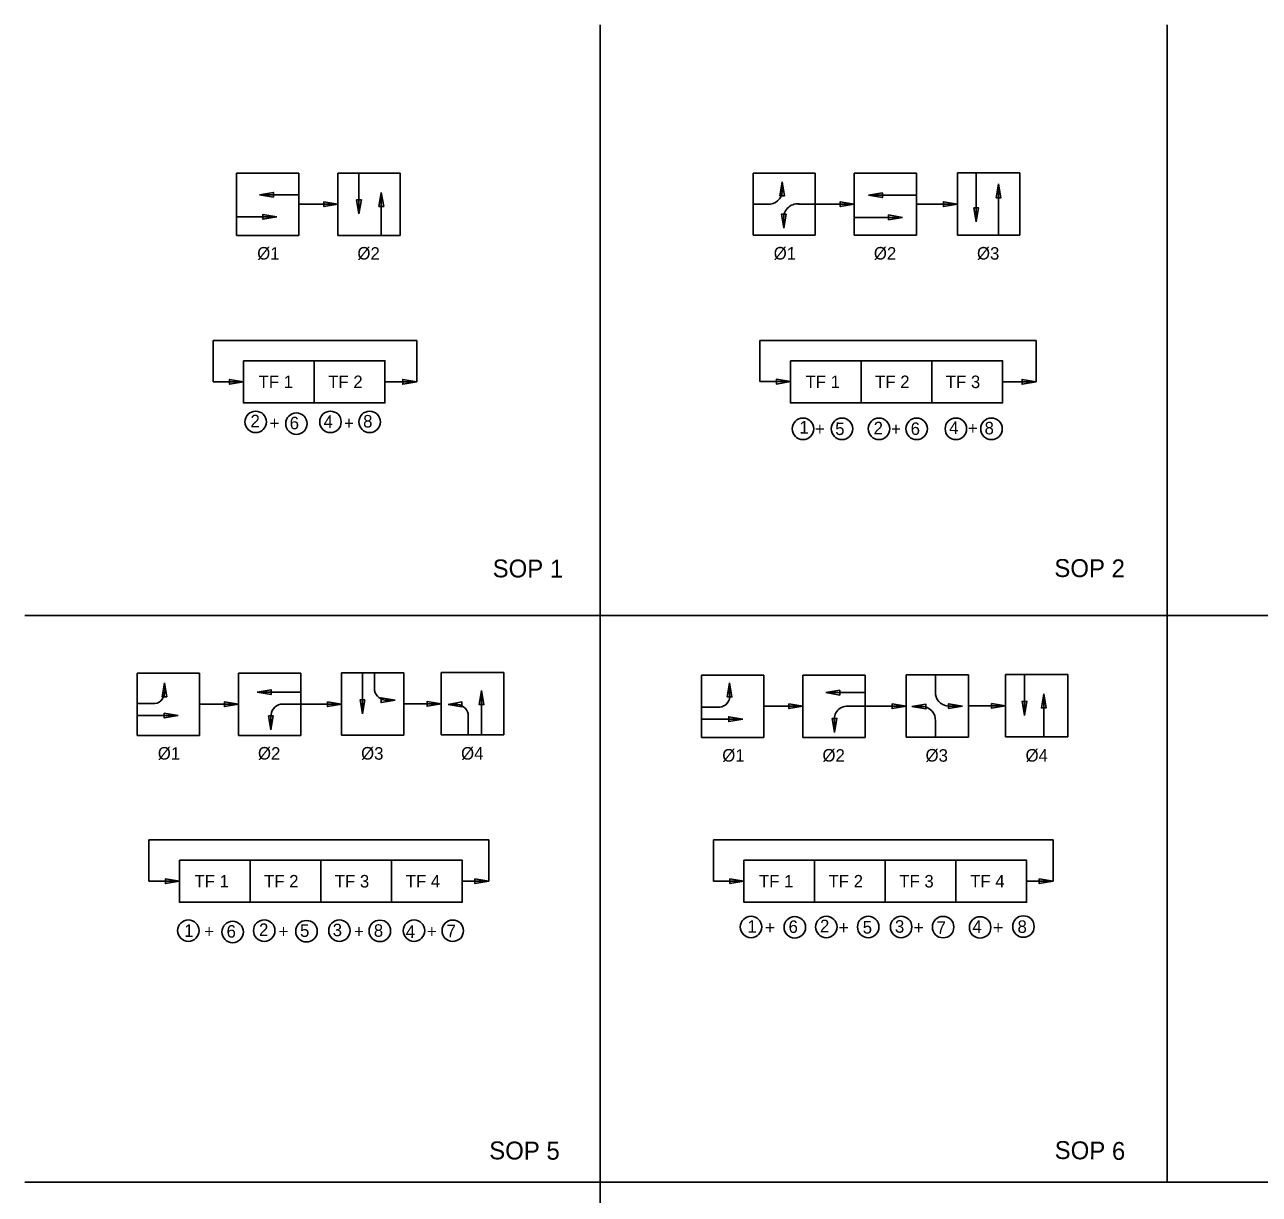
# Model space of a CAD drawing. Extents: x 10027 to 10796, y 10033 to 10528.
# Drawn here: x 10027.5 to 10372.3, y 10201.8 to 10528.4 of the extents above; entities that cross this region are included whole.
import ezdxf

# ---------------------------------------------------------------- set-up
doc = ezdxf.new("R2010")
doc.units = 0
for name, color, linetype in [('AdhocPoint_dp', 7, 'Continuous'), ('Default', 7, 'Continuous'), ('Dimension', 7, 'Continuous'), ('DSIndex', 7, 'Continuous'), ('PlotBorder_dp', 7, 'Continuous')]:
    doc.layers.add(name, color=color, linetype=linetype)

msp = doc.modelspace()

# ---------------------------------------------------------------- linework, layer by layer
at = {"layer": 'AdhocPoint_dp'}
for p, q in [((10188.25, 10033.43), (10188.25, 10528.43)), ((10346.55, 10205.22), (10346.55, 10528.43)), ((10027.5, 10363.43), (10662.13, 10363.43)), ((10662.13, 10205.22), (10027.5, 10205.22))]:
    msp.add_line(p, q, dxfattribs=at)
at = {"layer": 'Default'}
for p, q in [((10104.06, 10487), (10086.67, 10487)), ((10086.67, 10469.6), (10086.67, 10487)), ((10104.06, 10469.6), (10104.06, 10487)), ((10114.96, 10469.6), (10114.96, 10487)), ((10132.35, 10487), (10114.96, 10487)), ((10120.85, 10487), (10120.85, 10475.6)), ((10132.35, 10487), (10132.35, 10469.6)), ((10248.28, 10487.01), (10230.89, 10487.01)), ((10230.89, 10469.61), (10230.89, 10487.01)), ((10239.04, 10481.83), (10239.04, 10484.58)), ((10248.28, 10469.61), (10248.28, 10487.01)), ((10259.18, 10469.61), (10259.18, 10487.01)), ((10276.57, 10487.01), (10259.18, 10487.01)), ((10276.57, 10487.01), (10276.57, 10469.61)), ((10287.98, 10469.69), (10287.98, 10487.09)), ((10305.38, 10487.09), (10287.98, 10487.09)), ((10293.24, 10487.09), (10293.24, 10473.36)), ((10305.38, 10487.09), (10305.38, 10469.69)), ((10127.09, 10481.61), (10127.09, 10469.6)), ((10299.47, 10484.03), (10299.47, 10469.69)), ((10104.06, 10480.93), (10093.06, 10480.93)), ((10104.06, 10478.3), (10114.96, 10478.3)), ((10230.89, 10478.31), (10235.03, 10478.31)), ((10248.28, 10478.31), (10243.58, 10478.31)), ((10248.28, 10478.31), (10259.18, 10478.31)), ((10276.47, 10480.8), (10263.14, 10480.8)), ((10276.57, 10478.31), (10287.98, 10478.31)), ((10097.93, 10474.76), (10086.67, 10474.76)), ((10272.66, 10474.63), (10259.07, 10474.63)), ((10239.48, 10473.93), (10239.48, 10471.57)), ((10104.06, 10469.6), (10086.67, 10469.6)), ((10114.96, 10469.6), (10132.35, 10469.6)), ((10248.28, 10469.61), (10230.89, 10469.61)), ((10259.18, 10469.61), (10276.57, 10469.61)), ((10287.98, 10469.69), (10305.38, 10469.69)), ((10080.11, 10440.22), (10136.97, 10440.22)), ((10080.11, 10428.7), (10080.11, 10440.22)), ((10136.97, 10428.7), (10136.97, 10440.22)), ((10232.83, 10440.27), (10309.93, 10440.27)), ((10232.83, 10428.75), (10232.83, 10440.27)), ((10309.93, 10428.7), (10309.93, 10440.27)), ((10088.6, 10428.7), (10080.11, 10428.7)), ((10128.09, 10428.7), (10136.97, 10428.7)), ((10241.33, 10428.75), (10232.83, 10428.75)), ((10300.56, 10428.7), (10309.93, 10428.7)), ((10088.6, 10422.82), (10127.95, 10422.82)), ((10076.29, 10347.38), (10058.9, 10347.38)), ((10058.9, 10329.98), (10058.9, 10347.38)), ((10076.29, 10329.98), (10076.29, 10347.38)), ((10087.19, 10329.98), (10087.19, 10347.38)), ((10104.58, 10347.38), (10087.19, 10347.38)), ((10104.58, 10347.38), (10104.58, 10329.98)), ((10115.99, 10330.06), (10115.99, 10347.45)), ((10133.39, 10347.45), (10115.99, 10347.45)), ((10121.8, 10347.45), (10121.8, 10335.95)), ((10125.16, 10347.45), (10125.16, 10342.48)), ((10133.39, 10347.45), (10133.39, 10330.06)), ((10143.79, 10330.11), (10143.79, 10347.51)), ((10161.29, 10347.51), (10143.79, 10347.51)), ((10161.29, 10347.51), (10161.29, 10330.11)), ((10233.93, 10346.82), (10216.53, 10346.82)), ((10216.53, 10329.42), (10216.53, 10346.82)), ((10233.93, 10329.42), (10233.93, 10346.82)), ((10244.82, 10329.42), (10244.82, 10346.82)), ((10262.22, 10346.82), (10244.82, 10346.82)), ((10262.22, 10346.82), (10262.22, 10329.42)), ((10273.62, 10329.5), (10273.62, 10346.89)), ((10291.02, 10346.89), (10273.62, 10346.89)), ((10281.82, 10346.89), (10281.82, 10342.18)), ((10291.02, 10346.89), (10291.02, 10329.5)), ((10301.42, 10329.55), (10301.42, 10346.95)), ((10318.82, 10346.95), (10301.42, 10346.95)), ((10306.7, 10346.95), (10306.7, 10335.55)), ((10318.82, 10346.95), (10318.82, 10329.55)), ((10104.58, 10342.04), (10092.4, 10342.04)), ((10155.08, 10330.11), (10155.08, 10342.5)), ((10262.19, 10341.92), (10251.19, 10341.92)), ((10312.08, 10341.56), (10312.08, 10329.55)), ((10058.9, 10338.85), (10063.85, 10338.85)), ((10076.29, 10338.68), (10087.19, 10338.68)), ((10104.58, 10338.68), (10098.92, 10338.68)), ((10104.58, 10338.68), (10115.99, 10338.68)), ((10133.39, 10338.76), (10143.79, 10338.76)), ((10216.53, 10337.88), (10221.62, 10337.88)), ((10233.93, 10338.12), (10244.82, 10338.12)), ((10262.47, 10338.12), (10257.77, 10338.12)), ((10262.22, 10338.12), (10273.62, 10338.12)), ((10278.3, 10338.03), (10275.24, 10338.03)), ((10285.34, 10338.17), (10289.38, 10338.17)), ((10291.02, 10338.2), (10301.42, 10338.2)), ((10058.9, 10335.49), (10070.4, 10335.49)), ((10096.26, 10335.12), (10096.26, 10331.51)), ((10151.3, 10330.11), (10151.3, 10335.97)), ((10216.53, 10334.51), (10228.03, 10334.51)), ((10281.82, 10329.49), (10281.82, 10334.02)), ((10076.29, 10329.98), (10058.9, 10329.98)), ((10087.19, 10329.98), (10104.58, 10329.98)), ((10115.99, 10330.06), (10133.39, 10330.06)), ((10143.79, 10330.11), (10161.29, 10330.11)), ((10233.93, 10329.42), (10216.53, 10329.42)), ((10244.82, 10329.42), (10262.22, 10329.42)), ((10273.62, 10329.5), (10291.02, 10329.5)), ((10301.42, 10329.55), (10318.82, 10329.55)), ((10062.2, 10300.77), (10157.11, 10300.77)), ((10062.2, 10289.25), (10062.2, 10300.77)), ((10157.11, 10289.25), (10157.11, 10300.77)), ((10219.83, 10300.77), (10314.74, 10300.77)), ((10219.83, 10289.25), (10219.83, 10300.77)), ((10314.74, 10289.25), (10314.74, 10300.77)), ((10070.7, 10289.25), (10062.2, 10289.25)), ((10149.67, 10289.25), (10157.11, 10289.25)), ((10228.33, 10289.25), (10219.83, 10289.25)), ((10307.3, 10289.25), (10314.74, 10289.25))]:
    msp.add_line(p, q, dxfattribs=at)
for centre in [(10073.21, 10275.46), (10085.56, 10275.09), (10094.39, 10275.46), (10106.19, 10275.29), (10115.39, 10275.46), (10126.68, 10275.38), (10136.22, 10275.46), (10147.04, 10275.42), (10230.33, 10276.48), (10242.56, 10276.38), (10251.35, 10276.48), (10263.06, 10276.48), (10272.25, 10276.48), (10283.98, 10276.43), (10294.31, 10276.35), (10306.41, 10276.59)]:
    msp.add_circle(centre, 3, dxfattribs=at)
for centre, radius, start, end in [((10235.28, 10482.08), 3.78, 266.3242, 356.0955), ((10243.32, 10474.52), 3.88, 83.8256, 188.6991), ((10063.39, 10341.98), 3.16, 278.4278, 6.6131), ((10128.51, 10343.25), 3.44, 192.998, 272.423), ((10221.35, 10340.9), 3.03, 273.2123, 8.8094), ((10285.59, 10341.94), 3.78, 176.3242, 266.0955), ((10099.7, 10335.33), 3.44, 102.998, 183.455), ((10147.95, 10335.2), 3.44, 12.998, 92.3331), ((10257.26, 10334.49), 3.67, 82.0412, 192.3372), ((10278.05, 10334.26), 3.78, 356.3242, 86.0955)]:
    msp.add_arc(centre, radius, start, end, dxfattribs=at)
at = {"layer": 'Dimension'}
for p, q in [((10066.53, 10342.34), (10066.53, 10344.66)), ((10224.34, 10341.36), (10224.34, 10344.64)), ((10128.66, 10339.82), (10128.66, 10339.82)), ((10128.66, 10339.82), (10128.66, 10339.82)), ((10128.66, 10339.82), (10130.92, 10339.82)), ((10147.81, 10338.64), (10145.72, 10338.64)), ((10253.68, 10333.71), (10253.68, 10330.81))]:
    msp.add_line(p, q, dxfattribs=at)
for centre in [(10092.02, 10417.51), (10103.38, 10417.02), (10112.89, 10417.51), (10123.83, 10417.51), (10244.83, 10415.58), (10255.72, 10415.58), (10266.05, 10415.58), (10276.57, 10415.58), (10287.54, 10415.58), (10297.48, 10415.58)]:
    msp.add_circle(centre, 3, dxfattribs=at)
at = {"layer": 'DSIndex'}
for points in [[(10088.6, 10434.57), (10108.35, 10434.57), (10108.35, 10422.82), (10088.6, 10422.82)], [(10108.35, 10434.57), (10128.09, 10434.57), (10128.09, 10422.82), (10108.35, 10422.82)], [(10241.33, 10434.57), (10261.07, 10434.57), (10261.07, 10422.82), (10241.33, 10422.82)], [(10261.07, 10434.57), (10280.82, 10434.57), (10280.82, 10422.82), (10261.07, 10422.82)], [(10280.82, 10434.57), (10300.56, 10434.57), (10300.56, 10422.82), (10280.82, 10422.82)], [(10070.7, 10295.12), (10090.44, 10295.12), (10090.44, 10283.37), (10070.7, 10283.37)], [(10090.44, 10295.12), (10110.18, 10295.12), (10110.18, 10283.37), (10090.44, 10283.37)], [(10110.18, 10295.12), (10129.93, 10295.12), (10129.93, 10283.37), (10110.18, 10283.37)], [(10129.93, 10295.12), (10149.67, 10295.12), (10149.67, 10283.37), (10129.93, 10283.37)], [(10228.33, 10295.12), (10248.07, 10295.12), (10248.07, 10283.37), (10228.33, 10283.37)], [(10248.07, 10295.12), (10267.82, 10295.12), (10267.82, 10283.37), (10248.07, 10283.37)], [(10267.82, 10295.12), (10287.56, 10295.12), (10287.56, 10283.37), (10267.82, 10283.37)], [(10287.56, 10295.12), (10307.3, 10295.12), (10307.3, 10283.37), (10287.56, 10283.37)]]:
    msp.add_lwpolyline(points, close=True, dxfattribs=at)
at = {"layer": 'PlotBorder_dp'}
for points in [[(10239.04, 10484.58), (10238.38, 10480.68), (10239.71, 10480.68)], [(10093.06, 10480.93), (10096.97, 10480.27), (10096.97, 10481.59)], [(10127.09, 10481.61), (10126.43, 10477.7), (10127.75, 10477.7)], [(10263.14, 10480.8), (10267.04, 10480.13), (10267.04, 10481.46)], [(10299.47, 10484.03), (10298.81, 10480.12), (10300.13, 10480.12)], [(10114.96, 10478.3), (10111.05, 10478.96), (10111.05, 10477.64)], [(10120.85, 10475.6), (10121.52, 10479.51), (10120.19, 10479.51)], [(10259.18, 10478.31), (10255.27, 10478.97), (10255.27, 10477.65)], [(10287.98, 10478.31), (10284.08, 10478.97), (10284.08, 10477.65)], [(10097.93, 10474.76), (10094.02, 10475.43), (10094.02, 10474.1)], [(10239.48, 10471.57), (10240.14, 10475.48), (10238.82, 10475.48)], [(10272.66, 10474.63), (10268.76, 10475.29), (10268.76, 10473.97)], [(10293.24, 10473.36), (10293.9, 10477.27), (10292.58, 10477.27)], [(10088.6, 10428.7), (10084.7, 10429.36), (10084.7, 10428.03)], [(10136.97, 10428.7), (10133.07, 10429.36), (10133.07, 10428.03)], [(10241.33, 10428.75), (10237.42, 10429.41), (10237.42, 10428.09)], [(10309.93, 10428.7), (10306.02, 10429.36), (10306.02, 10428.03)], [(10066.53, 10344.66), (10065.87, 10340.76), (10067.19, 10340.76)], [(10224.34, 10344.64), (10223.68, 10340.73), (10225, 10340.73)], [(10092.4, 10342.04), (10096.31, 10341.38), (10096.31, 10342.71)], [(10121.8, 10335.95), (10122.46, 10339.86), (10121.14, 10339.86)], [(10130.92, 10339.82), (10127.02, 10340.48), (10127.02, 10339.15)], [(10155.08, 10342.5), (10154.42, 10338.59), (10155.74, 10338.59)], [(10251.19, 10341.92), (10255.09, 10341.25), (10255.09, 10342.58)], [(10312.08, 10341.56), (10311.41, 10337.65), (10312.74, 10337.65)], [(10087.19, 10338.68), (10083.28, 10339.34), (10083.28, 10338.02)], [(10115.99, 10338.68), (10112.09, 10339.34), (10112.09, 10338.02)], [(10143.79, 10338.76), (10139.88, 10339.42), (10139.88, 10338.09)], [(10145.72, 10338.64), (10149.62, 10337.98), (10149.62, 10339.3)], [(10244.82, 10338.12), (10240.92, 10338.78), (10240.92, 10337.46)], [(10273.62, 10338.12), (10269.72, 10338.78), (10269.72, 10337.46)], [(10275.24, 10338.03), (10279.15, 10337.37), (10279.15, 10338.69)], [(10289.38, 10338.17), (10285.48, 10338.83), (10285.48, 10337.51)], [(10301.42, 10338.2), (10297.52, 10338.86), (10297.52, 10337.54)], [(10306.7, 10335.55), (10307.36, 10339.46), (10306.04, 10339.46)], [(10070.4, 10335.49), (10066.49, 10336.15), (10066.49, 10334.83)], [(10096.26, 10331.51), (10096.92, 10335.42), (10095.6, 10335.42)], [(10228.03, 10334.51), (10224.13, 10335.17), (10224.13, 10333.85)], [(10253.68, 10330.81), (10254.34, 10334.71), (10253.02, 10334.71)], [(10070.7, 10289.25), (10066.79, 10289.91), (10066.79, 10288.59)], [(10157.11, 10289.25), (10153.21, 10289.91), (10153.21, 10288.59)], [(10228.33, 10289.25), (10224.42, 10289.91), (10224.42, 10288.59)], [(10314.74, 10289.25), (10310.84, 10289.91), (10310.84, 10288.59)]]:
    msp.add_lwpolyline(points, close=True, dxfattribs=at)

# ---------------------------------------------------------------- texts
at = {"layer": 'Default'}
for s, height, p in [('TF 1', 3.5, (10092.82, 10426.95)), ('TF 2', 3.5, (10112.25, 10426.95)), ('TF 1', 3.5, (10245.55, 10426.95)), ('TF 2', 3.5, (10264.98, 10426.95)), ('TF 3', 3.5, (10284.72, 10426.95)), ('TF 1', 3.5, (10074.91, 10287.5)), ('TF 2', 3.5, (10094.34, 10287.5)), ('TF 3', 3.5, (10114.09, 10287.5)), ('TF 4', 3.5, (10133.9, 10287.5)), ('TF 1', 3.5, (10232.55, 10287.5)), ('TF 2', 3.5, (10251.98, 10287.5)), ('TF 3', 3.5, (10271.72, 10287.5)), ('TF 4', 3.5, (10291.53, 10287.5)), ('+', 3.5, (10077.65, 10273.52)), ('+', 3.5, (10098.41, 10273.52)), ('+', 3.5, (10119.47, 10273.52)), ('+', 3.5, (10139.84, 10273.52)), ('+', 3.78, (10234.13, 10274.46)), ('+', 3.78, (10254.72, 10274.46)), ('+', 3.78, (10275.66, 10274.46)), ('+', 3.78, (10297.87, 10274.46))]:
    msp.add_text(s, height=height, dxfattribs=at).set_placement(p)
for s, height, rotation, p in [('SOP 1', 5, 359.6902, (10158.17, 10374.11)), ('SOP 2', 5, 359.6902, (10315.03, 10374.21)), ('1', 3.5, 359.6943, (10229.31, 10274.86)), ('6', 3.5, 359.6943, (10240.81, 10274.82)), ('2', 3.5, 359.6943, (10249.59, 10275.02)), ('5', 3.5, 359.6943, (10261.52, 10274.62)), ('3', 3.5, 359.6943, (10270.52, 10274.88)), ('7', 3.5, 359.6943, (10282.14, 10274.54)), ('4', 3.5, 359.6943, (10292.14, 10274.82)), ('8', 3.5, 359.6943, (10304.75, 10274.83)), ('1', 3.5, 359.6943, (10072.05, 10273.72)), ('6', 3.5, 359.6943, (10083.87, 10273.51)), ('2', 3.5, 359.6943, (10092.93, 10273.97)), ('5', 3.5, 359.6943, (10104.39, 10273.7)), ('3', 3.5, 359.6943, (10113.51, 10273.89)), ('8', 3.5, 359.6943, (10124.99, 10273.74)), ('4', 3.5, 359.6943, (10133.89, 10273.45)), ('7', 3.5, 359.6943, (10145.29, 10273.6)), ('SOP 5', 5, 359.6902, (10157.21, 10211.59)), ('SOP 6', 5, 359.1183, (10315.1, 10211.71))]:
    msp.add_text(s, height=height, rotation=rotation, dxfattribs=at).set_placement(p)
at = {"layer": 'Dimension'}
for s, rotation, p in [('Ø1', 359.1183, (10092.41, 10462.88)), ('Ø2', 359.1183, (10120.39, 10462.88)), ('Ø1', 359.1183, (10236.64, 10462.89)), ('Ø2', 359.1183, (10264.61, 10462.89)), ('Ø3', 359.1183, (10293.41, 10462.89)), ('2', 359.6943, (10090.55, 10416.02)), ('6', 359.6943, (10101.49, 10415.47)), ('4', 359.6943, (10110.96, 10415.84)), ('8', 359.6943, (10122, 10415.95)), ('1', 359.6943, (10243.86, 10414.27)), ('5', 359.6943, (10253.83, 10413.85)), ('2', 359.6943, (10264.57, 10414.06)), ('6', 359.6943, (10274.9, 10413.89)), ('4', 359.6943, (10285.65, 10414.14)), ('8', 359.6943, (10295.54, 10414.04)), ('Ø1', 359.1183, (10064.65, 10323.25)), ('Ø2', 359.1183, (10092.62, 10323.26)), ('Ø3', 359.1183, (10121.42, 10323.26)), ('Ø1', 359.1183, (10222.28, 10322.69)), ('Ø2', 359.1183, (10250.25, 10322.7)), ('Ø3', 359.1183, (10279.05, 10322.7))]:
    msp.add_text(s, height=3.5, rotation=rotation, dxfattribs=at).set_placement(p)
for s, p in [('+', (10095.9, 10415.44)), ('+', (10116.71, 10415.44)), ('+', (10248.17, 10413.82)), ('+', (10269.43, 10413.82)), ('+', (10290.91, 10414.03)), ('Ø4', (10149.37, 10323.21)), ('Ø4', (10307, 10322.65))]:
    msp.add_text(s, height=3.5, dxfattribs=at).set_placement(p)

doc.saveas('drawing.dxf')
